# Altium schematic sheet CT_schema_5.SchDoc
size 278 x 170 mm
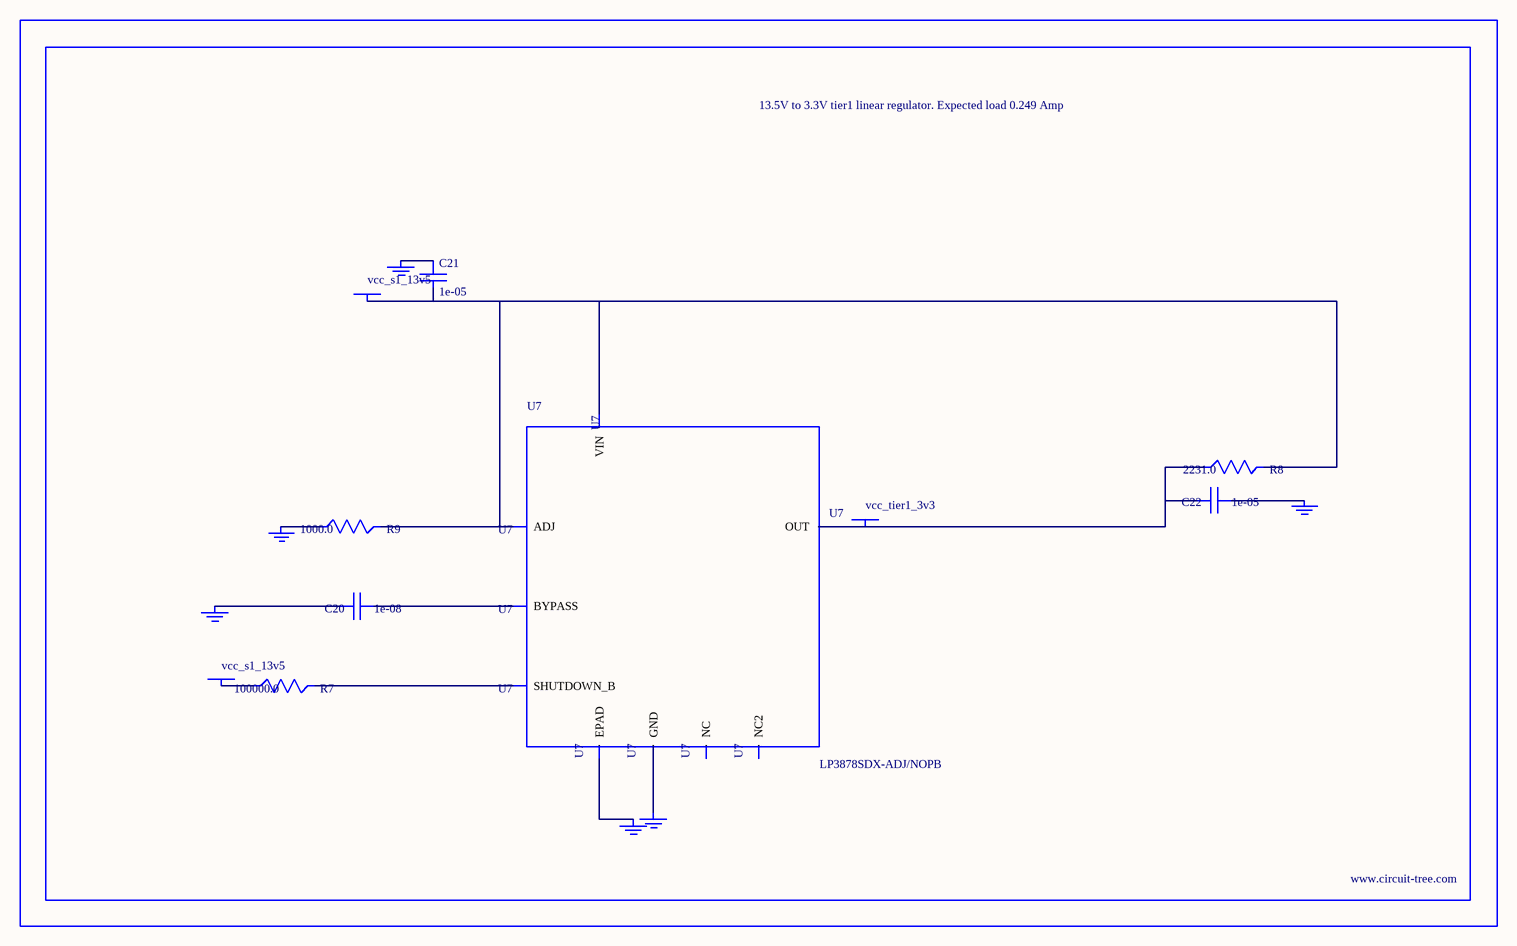
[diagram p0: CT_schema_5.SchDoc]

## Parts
BORDER4  (no value)
C20  1e-08  [C0402]
C21  1e-05  [C1210]
C22  1e-05  [C1210]
GND_INSTANCE_4_0  (no value)
GND_INSTANCE_4_1  (no value)
GND_INSTANCE_4_2  (no value)
GND_INSTANCE_4_3  (no value)
GND_INSTANCE_4_4  (no value)
GND_INSTANCE_4_5  (no value)
POWER_INSTANCE_4_0  vcc_s1_13v5
POWER_INSTANCE_4_1  vcc_s1_13v5
POWER_INSTANCE_4_2  vcc_tier1_3v3
R7  100000.0  [R0603]
R8  2231.0  [R0603]
R9  1000.0  [R0603]
U7  LP3878SDX-ADJ/NOPB  [WSON-8]

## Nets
NetC20_1: C20.1 U7.1(BYPASS)
NetC20_2: C20.2 GND_INSTANCE_4_0.0(GND)
NetC21_1: C21.1 GND_INSTANCE_4_1.0(GND)
NetC21_2: C21.2 POWER_INSTANCE_4_0.0(PWR) R8.2 R9.2 U7.4(VIN) U7.6(ADJ)
NetC22_1: C22.1 GND_INSTANCE_4_2.0(GND)
NetC22_2: C22.2 POWER_INSTANCE_4_2.0(PWR) R8.1 U7.5(OUT)
NetGND_INSTANCE_4_3_0: GND_INSTANCE_4_3.0(GND) R9.1
NetGND_INSTANCE_4_4_0: GND_INSTANCE_4_4.0(GND) U7.PAD(EPAD)
NetGND_INSTANCE_4_5_0: GND_INSTANCE_4_5.0(GND) U7.3(GND)
NetPOWER_INSTANCE_4_1_0: POWER_INSTANCE_4_1.0(PWR) R7.1
NetR7_2: R7.2 U7.8(SHUTDOWN_B)

Not connected (* = marked no-connect by the designer): U7 2(NC) 7(NC2)

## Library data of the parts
BORDER4 = BORDER_PAGE4
C20 = C0402C103K3RAC
C21 = C1210C106K5PACTU
C22 = GRM32DR61E106MA12L
GND_INSTANCE_4_0-GND_INSTANCE_4_5 = GND
POWER_INSTANCE_4_0-POWER_INSTANCE_4_2 = PWR
R7 = RC0603JR-07100KL
R8 = R8
R9 = RC0603JR-071KL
